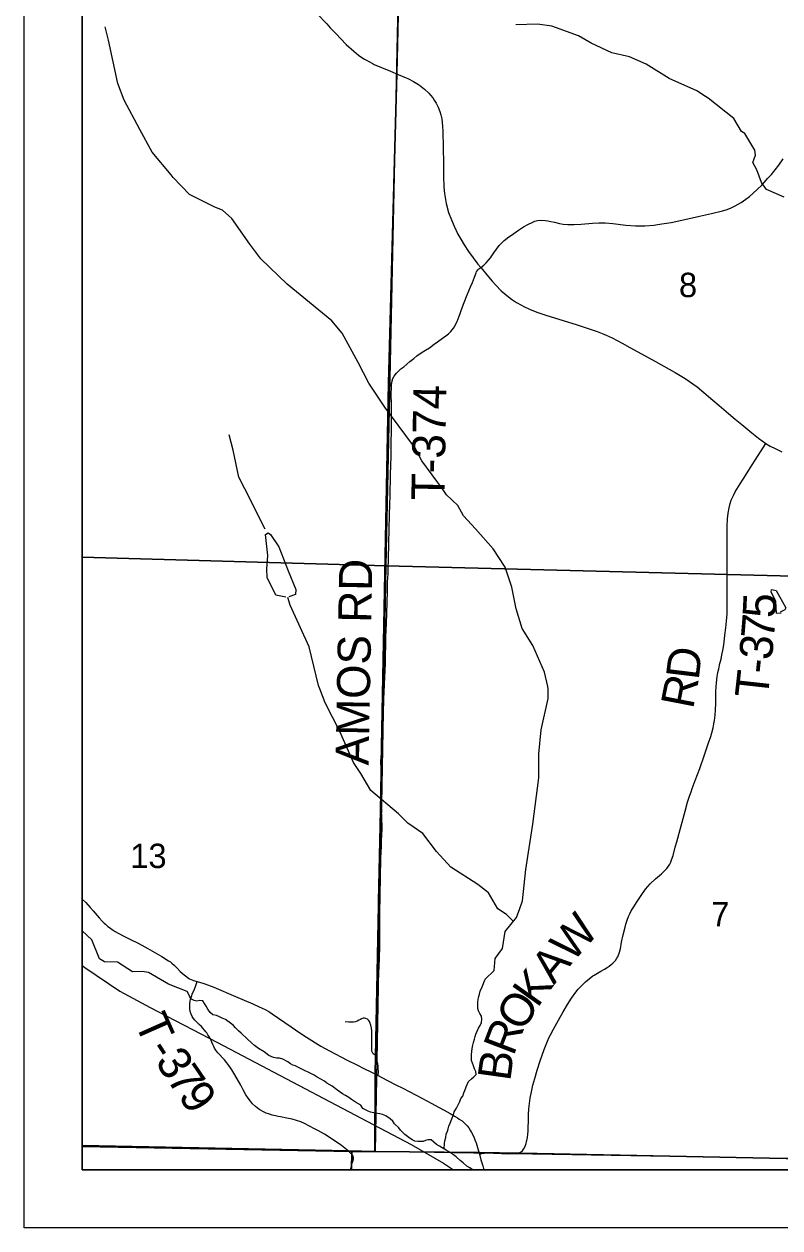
# Model space of a CAD drawing. Extents: x 0 to 34, y 0 to 22.
# Drawn here: x 2.5 to 3.798, y 13.5 to 15.568 of the extents above; entities that cross this region are included whole.
import ezdxf

# ---------------------------------------------------------------- set-up
doc = ezdxf.new("R2010")
doc.units = 0
for name, color, linetype in [('GM_X_Corporation', 7, 'Continuous'), ('GM_X_County_Road', 7, 'Continuous'), ('GM_X_Minor_River', 7, 'Continuous'), ('GM_X_Rail_Line', 7, 'Continuous'), ('GM_X_Section_Text', 7, 'Continuous'), ('GM_X_State_Route', 7, 'Continuous'), ('GM_X_Township_Road', 7, 'Continuous'), ('GM_X_Township_Road_Text', 7, 'Continuous'), ('SH_Data', 7, 'Continuous')]:
    doc.layers.add(name, color=color, linetype=linetype)

msp = doc.modelspace()

# ---------------------------------------------------------------- linework, layer by layer
at = {"layer": 'GM_X_Corporation'}
for points in [[(2.6, 16.6918), (2.6, 13.6), (9.4, 13.6), (9.4, 16.4853), (9.09, 16.4927), (8.0963, 16.5226), (6.2194, 16.578), (6.0834, 16.5816), (5.4202, 16.5982), (4.6351, 16.6229), (4.5473, 16.6256), (4.1867, 16.6352), (4.1011, 16.6362), (4.0515, 16.6368), (3.1684, 16.6682), (3.1555, 16.6686)], [(2.6, 16.6918), (2.6, 13.6417), (3.0575, 13.6324), (3.1025, 13.6315), (3.1033, 13.7653), (3.1089, 14.0542), (3.109, 14.0614), (3.1121, 14.2169), (3.1127, 14.2486), (3.1134, 14.2853), (3.1142, 14.3277), (3.1263, 14.9513), (3.1401, 15.483), (3.148, 15.8071), (3.1555, 16.6686)], [(2.6, 15.673), (2.6, 14.6526), (3.1218, 14.6372), (3.1435, 15.6571)], [(4.1616, 15.6255), (4.1372, 14.6117), (3.1218, 14.6372), (3.1435, 15.6571)], [(2.6, 14.6526), (2.6, 13.6399), (3.0633, 13.6314), (3.1037, 13.6311), (3.1218, 14.6372)], [(3.1218, 14.6372), (4.1372, 14.6117), (4.1159, 13.6143), (3.1037, 13.6311)], [(2.6, 13.6417), (2.6, 13.6), (4.5781, 13.6), (4.3222, 13.6092), (3.3525, 13.6282), (3.2812, 13.6297), (3.1025, 13.6315), (3.0575, 13.6324)], [(2.6, 13.6399), (2.6, 13.6), (3.0626, 13.6), (3.0633, 13.6314)], [(3.0626, 13.6), (4.1154, 13.6), (4.1159, 13.6143), (3.1037, 13.6311), (3.0633, 13.6314)]]:
    msp.add_lwpolyline(points, close=True, dxfattribs=at)
msp.add_lwpolyline([(3.1555, 16.6686), (3.148, 15.8071), (3.1401, 15.483), (3.1263, 14.9513), (3.1142, 14.3277), (3.1134, 14.2853), (3.1127, 14.2486), (3.1121, 14.2169), (3.109, 14.0614), (3.1089, 14.0542), (3.1033, 13.7653), (3.1025, 13.6315), (3.2812, 13.6297), (3.3525, 13.6282), (4.3222, 13.6092), (4.5781, 13.6), (9.4, 13.6)], dxfattribs=at)
at = {"layer": 'GM_X_County_Road'}
for points in [[(2.6, 14.065), (2.606, 14.0588), (2.6135, 14.0506), (2.6189, 14.0445), (2.6289, 14.0329), (2.6344, 14.0269), (2.6371, 14.0243), (2.6377, 14.0237), (2.6396, 14.0219), (2.6441, 14.0181), (2.6465, 14.0163), (2.6515, 14.0126), (2.6566, 14.0093), (2.6619, 14.0062), (2.6711, 14.0012), (2.6842, 13.9947), (2.6949, 13.9896), (2.7022, 13.986), (2.7128, 13.9803), (2.7208, 13.9756), (2.7365, 13.9665), (2.7483, 13.9591), (2.7515, 13.9569), (2.7538, 13.9551), (2.758, 13.9513), (2.7629, 13.9461), (2.7684, 13.9405), (2.7748, 13.9346), (2.7771, 13.9328), (2.7825, 13.9292), (2.7843, 13.9282), (2.7899, 13.9258), (2.7912, 13.9253), (2.7974, 13.9233), (2.7993, 13.9228), (2.8054, 13.9211), (2.8107, 13.9194), (2.8261, 13.9134), (2.8634, 13.8977), (2.8779, 13.8913), (2.8927, 13.885), (2.9038, 13.8801), (2.9142, 13.875), (2.9204, 13.8716), (2.9223, 13.8704), (2.9263, 13.8678), (2.9372, 13.8604), (2.9587, 13.8454), (2.9736, 13.8354), (2.9851, 13.8279), (3.01, 13.8124), (3.0245, 13.8041), (3.0548, 13.7884), (3.0715, 13.7799), (3.0847, 13.7735), (3.0956, 13.768), (3.1023, 13.7646)], [(3.1023, 13.7646), (3.1081, 13.7618), (3.1133, 13.7592), (3.1374, 13.7466), (3.1519, 13.7393), (3.1605, 13.7347), (3.1747, 13.7273), (3.2007, 13.7136), (3.2121, 13.7077), (3.2215, 13.7025), (3.232, 13.6965), (3.2403, 13.6915), (3.2444, 13.6889), (3.2474, 13.687), (3.2513, 13.6844), (3.2524, 13.6837), (3.2566, 13.6802), (3.2611, 13.6755), (3.264, 13.6717), (3.2669, 13.667), (3.2685, 13.6642), (3.2718, 13.6578), (3.2731, 13.6549), (3.2744, 13.6515), (3.2761, 13.6475), (3.2766, 13.6462), (3.28, 13.634), (3.2822, 13.6266)], [(3.2822, 13.6266), (3.2835, 13.6217), (3.2839, 13.6201), (3.2848, 13.6172)], [(3.2848, 13.6172), (3.2878, 13.6065), (3.2899, 13.6)]]:
    msp.add_lwpolyline(points, dxfattribs=at)
at = {"layer": 'GM_X_Minor_River'}
for points in [[(3.2868, 13.9142), (3.2923, 13.9274), (3.3076, 13.9424), (3.3092, 13.9629), (3.3218, 13.9802), (3.3263, 14.0094), (3.3461, 14.0332), (3.3516, 14.0488), (3.3563, 14.0622), (3.362, 14.1157), (3.3737, 14.1936), (3.3843, 14.273), (3.3841, 14.3143), (3.3884, 14.3557), (3.4001, 14.4097), (3.4003, 14.426), (3.3995, 14.4302), (3.3938, 14.4547), (3.3737, 14.5007), (3.3555, 14.5296), (3.3455, 14.5636), (3.3377, 14.601), (3.3266, 14.635), (3.306, 14.6665), (3.2752, 14.701), (3.2551, 14.7234), (3.245, 14.7411), (3.2254, 14.7594), (3.2188, 14.7695), (3.1835, 14.8179), (3.1714, 14.8408), (3.1675, 14.8461), (3.1199, 14.9102), (3.0924, 14.9515), (3.074, 14.9869), (3.0467, 15.0369), (3.0286, 15.0586), (2.9521, 15.1215), (2.9067, 15.1648), (2.8877, 15.1899), (2.8567, 15.2342), (2.8406, 15.2487), (2.8276, 15.2538), (2.784, 15.2752), (2.7563, 15.3043), (2.7528, 15.3092), (2.72, 15.3481), (2.6989, 15.3868), (2.672, 15.4376), (2.6609, 15.4662), (2.645, 15.5406), (2.6394, 15.5633)], [(3.8056, 15.2709), (3.7751, 15.2838), (3.7665, 15.2958), (3.7586, 15.318), (3.7516, 15.3304), (3.7567, 15.343), (3.7555, 15.3513), (3.7384, 15.3803), (3.7326, 15.3836), (3.719, 15.4058), (3.6749, 15.4411), (3.6706, 15.4437), (3.6557, 15.4537), (3.608, 15.4746), (3.5689, 15.4995), (3.5402, 15.5119), (3.5094, 15.5187), (3.4742, 15.5356), (3.4524, 15.5478), (3.4066, 15.5645), (3.3819, 15.568), (3.3448, 15.567)], [(2.9139, 14.7002), (2.8795, 14.7698), (2.869, 14.7897), (2.8592, 14.8362), (2.8523, 14.8626)], [(2.9498, 14.5836), (2.9323, 14.5871), (2.9174, 14.6172), (2.9172, 14.6324), (2.9188, 14.6551), (2.9148, 14.6915), (2.9193, 14.6942), (2.9235, 14.6912), (2.9379, 14.6702), (2.9537, 14.6291), (2.9667, 14.5967), (2.9664, 14.5884), (2.9547, 14.584)], [(3.3406, 14.0266), (3.329, 14.0386), (3.3136, 14.0483), (3.298, 14.0757), (3.2792, 14.0899), (3.2329, 14.1199), (3.2082, 14.1465), (3.185, 14.1776), (3.1593, 14.1954), (3.1431, 14.2111), (3.0955, 14.2517), (3.0787, 14.2807), (3.0659, 14.2994), (3.0424, 14.3529), (3.017, 14.4018), (3.0079, 14.4263), (3.0055, 14.432), (2.9898, 14.4985), (2.9572, 14.57), (2.9528, 14.5832)], [(3.8006, 14.5562), (3.7923, 14.5553), (3.7912, 14.5766), (3.7834, 14.5924), (3.7837, 14.5965), (3.7917, 14.5948), (3.8088, 14.5654), (3.807, 14.5616), (3.799, 14.5581)], [(2.7799, 13.9062), (2.7479, 13.9186), (2.7138, 13.9386), (2.7031, 13.9403), (2.6861, 13.9397), (2.6604, 13.9564), (2.6384, 13.9572), (2.6296, 13.9623), (2.6162, 13.9947), (2.6, 14.0101)], [(2.8838, 13.8242), (2.8731, 13.8348), (2.8685, 13.8385), (2.8631, 13.8438), (2.86, 13.8479), (2.8546, 13.8517), (2.8458, 13.8581), (2.8404, 13.8603), (2.8347, 13.8633), (2.8305, 13.8647), (2.824, 13.8658), (2.8194, 13.8703), (2.8159, 13.8756), (2.8128, 13.8809), (2.8097, 13.8854), (2.807, 13.89), (2.8021, 13.8907), (2.7968, 13.8898), (2.7922, 13.8906), (2.7876, 13.8928), (2.7845, 13.8972), (2.7822, 13.9021), (2.7799, 13.9062)], [(3.2216, 13.6357), (3.2224, 13.6449), (3.2228, 13.6498), (3.2246, 13.6556), (3.2253, 13.6609), (3.2272, 13.6662), (3.2283, 13.6704), (3.2297, 13.6746), (3.232, 13.68), (3.2349, 13.6876), (3.2379, 13.6941), (3.239, 13.6994), (3.2427, 13.7059), (3.245, 13.7101), (3.2487, 13.7174), (3.2505, 13.7223), (3.2539, 13.7265), (3.2554, 13.7319), (3.2569, 13.7361), (3.2595, 13.7422), (3.2609, 13.7464), (3.2632, 13.7517), (3.2685, 13.7563), (3.2726, 13.7594), (3.2767, 13.7636), (3.2759, 13.7689), (3.2736, 13.7735), (3.272, 13.7784), (3.2701, 13.7829), (3.2685, 13.7875), (3.2685, 13.7928), (3.2688, 13.7973), (3.2691, 13.8038), (3.2705, 13.8114), (3.272, 13.8186), (3.2735, 13.8244), (3.2749, 13.8289), (3.276, 13.8331), (3.2786, 13.8381), (3.2809, 13.843), (3.2835, 13.848), (3.2857, 13.853), (3.2864, 13.8587), (3.2856, 13.864), (3.2829, 13.8681), (3.2806, 13.8731), (3.2797, 13.8772), (3.2793, 13.8822), (3.2796, 13.8875), (3.2803, 13.8928), (3.2814, 13.8974), (3.2825, 13.9016), (3.2832, 13.9065), (3.2868, 13.9142)], [(3.2705, 13.6), (3.2697, 13.6005), (3.2655, 13.6032), (3.2605, 13.6061), (3.2544, 13.6118), (3.249, 13.6159), (3.2421, 13.6219), (3.2332, 13.6291), (3.2252, 13.6335), (3.2183, 13.6376), (3.2137, 13.6403), (3.2084, 13.6432), (3.2038, 13.6474), (3.1992, 13.6511), (3.1938, 13.6511), (3.1896, 13.6503), (3.1855, 13.6483), (3.1764, 13.6482), (3.1714, 13.649), (3.1668, 13.6516), (3.1607, 13.6553), (3.1538, 13.6606), (3.1469, 13.6677), (3.1438, 13.6722), (3.1365, 13.679), (3.1334, 13.6835), (3.1288, 13.6873), (3.1215, 13.6925), (3.1158, 13.6947), (3.1112, 13.6958), (3.1035, 13.6973), (3.0952, 13.6991), (3.0902, 13.701), (3.0818, 13.7054), (3.0783, 13.7111), (3.0691, 13.7159), (3.0622, 13.7204), (3.058, 13.7242), (3.0522, 13.7275), (3.0469, 13.7305), (3.0369, 13.7376), (3.0293, 13.7433), (3.0201, 13.7489), (3.0158, 13.7523), (3.0032, 13.759), (2.9986, 13.7627), (2.9902, 13.7664), (2.9806, 13.7709), (2.9703, 13.7761), (2.9661, 13.7787), (2.9619, 13.7798), (2.9577, 13.7817), (2.9531, 13.7851), (2.9447, 13.7899), (2.939, 13.7914), (2.934, 13.7917), (2.9287, 13.7928), (2.9206, 13.7961), (2.9122, 13.8025), (2.9026, 13.8081), (2.8961, 13.8134), (2.8907, 13.8179), (2.8838, 13.8242)]]:
    msp.add_lwpolyline(points, dxfattribs=at)
at = {"layer": 'GM_X_Rail_Line'}
msp.add_lwpolyline([(2.6, 13.9509), (2.6043, 13.9472), (2.6645, 13.9065), (2.7166, 13.8785), (2.8323, 13.8188), (3.1651, 13.6431), (3.2204, 13.6113), (3.2374, 13.6)], dxfattribs=at)
at = {"layer": 'GM_X_State_Route'}
for points in [[(3.0036, 15.5859), (3.0198, 15.5683), (3.026, 15.5619), (3.0353, 15.5522), (3.0534, 15.5332), (3.0666, 15.5215), (3.0745, 15.5149), (3.0767, 15.5133), (3.085, 15.508), (3.0869, 15.5068), (3.0996, 15.4998), (3.1012, 15.4989), (3.114, 15.4933), (3.1293, 15.487), (3.1425, 15.4814)], [(3.1425, 15.4814), (3.1533, 15.4772), (3.1553, 15.4763), (3.1604, 15.4739), (3.1687, 15.4697), (3.1774, 15.4646), (3.1794, 15.4632), (3.1881, 15.4566), (3.1954, 15.4494), (3.1983, 15.4461), (3.2022, 15.4412), (3.2044, 15.4377), (3.2077, 15.4325), (3.2111, 15.4255), (3.214, 15.418), (3.2158, 15.4123), (3.2174, 15.4051), (3.2183, 15.3988), (3.2188, 15.3928), (3.2193, 15.3836), (3.2196, 15.3722), (3.2197, 15.3677), (3.2198, 15.3587), (3.2203, 15.3259), (3.2207, 15.2998), (3.2208, 15.2952), (3.2212, 15.2879), (3.2221, 15.277), (3.2231, 15.27), (3.2249, 15.2598), (3.2293, 15.2443), (3.234, 15.2319), (3.2389, 15.2208), (3.245, 15.2075), (3.2501, 15.1984), (3.2561, 15.1887), (3.2637, 15.1776), (3.2713, 15.1667), (3.2777, 15.158), (3.2795, 15.1557), (3.2846, 15.1499), (3.2873, 15.1465), (3.2949, 15.1371), (3.3042, 15.1264), (3.3106, 15.1194), (3.3197, 15.11), (3.3257, 15.1047), (3.332, 15.0997), (3.3372, 15.0958), (3.3393, 15.0943), (3.3444, 15.091), (3.3461, 15.0898), (3.3544, 15.085), (3.3586, 15.0828), (3.3683, 15.0783), (3.381, 15.0734), (3.3965, 15.0681), (3.4129, 15.0628), (3.4483, 15.0518), (3.4671, 15.0457), (3.4847, 15.0398), (3.4961, 15.0354), (3.5002, 15.0336), (3.5101, 15.029), (3.5277, 15.0198), (3.5408, 15.0127), (3.5732, 14.9947), (3.5847, 14.9883), (3.6083, 14.9752), (3.6182, 14.9695), (3.6273, 14.9642), (3.6356, 14.959), (3.643, 14.9542), (3.6488, 14.9502), (3.656, 14.9448), (3.6678, 14.9352), (3.6757, 14.9284), (3.6833, 14.9218), (3.6939, 14.913), (3.71, 14.8993), (3.7218, 14.8894), (3.7329, 14.8804), (3.75, 14.8661), (3.7618, 14.8569), (3.7677, 14.8522), (3.7742, 14.8478), (3.7816, 14.8433), (3.7903, 14.8388), (3.8019, 14.8332)]]:
    msp.add_lwpolyline(points, dxfattribs=at)
at = {"layer": 'GM_X_Township_Road'}
for points in [[(3.2846, 15.1499), (3.2897, 15.1541), (3.2938, 15.1579), (3.2976, 15.1624), (3.3011, 15.1668), (3.307, 15.1751), (3.3164, 15.1878), (3.3205, 15.1922), (3.3248, 15.1963), (3.3328, 15.2025), (3.3371, 15.2057), (3.3493, 15.2141), (3.3582, 15.2199), (3.3665, 15.2246), (3.3726, 15.2274), (3.3775, 15.2293), (3.3818, 15.2305), (3.3865, 15.2311), (3.3954, 15.2308), (3.3995, 15.2302), (3.4049, 15.2292), (3.4114, 15.2278), (3.4197, 15.2257), (3.4263, 15.2246), (3.434, 15.2238), (3.445, 15.2236), (3.4571, 15.2243), (3.4764, 15.2261), (3.4874, 15.2268), (3.4982, 15.2266), (3.5112, 15.2256), (3.5339, 15.2229), (3.5506, 15.2216), (3.5664, 15.2218), (3.5818, 15.2228), (3.5955, 15.2247), (3.6116, 15.2275), (3.6348, 15.2323), (3.66, 15.238), (3.681, 15.2428), (3.6999, 15.2472), (3.7062, 15.249), (3.7134, 15.252), (3.7217, 15.2561), (3.7318, 15.2619), (3.74, 15.2676), (3.7459, 15.272), (3.7521, 15.2773), (3.7673, 15.2915), (3.7747, 15.3), (3.7771, 15.3027), (3.7815, 15.3073), (3.7837, 15.3098), (3.7963, 15.3258), (3.8041, 15.3364)], [(3.1316, 14.9514), (3.1323, 14.9552), (3.1337, 14.959), (3.1358, 14.9635), (3.1398, 14.9687), (3.1473, 14.9756), (3.1522, 14.9795), (3.1575, 14.9841), (3.1629, 14.9885), (3.1693, 14.9939), (3.1748, 14.9981), (3.1824, 15.0032), (3.1897, 15.0077), (3.1964, 15.0122), (3.2047, 15.0181), (3.2103, 15.0221), (3.219, 15.0283), (3.2244, 15.0324), (3.2289, 15.0362), (3.2329, 15.0402), (3.2374, 15.0455), (3.2392, 15.048), (3.2418, 15.0529), (3.2437, 15.0572), (3.2491, 15.0707), (3.2511, 15.0763), (3.2534, 15.0826), (3.2561, 15.0896), (3.2612, 15.1028), (3.267, 15.1167), (3.2701, 15.124), (3.2736, 15.1336), (3.2764, 15.141), (3.2772, 15.1428), (3.2781, 15.1442), (3.2795, 15.1459), (3.2813, 15.1475), (3.2846, 15.1499)], [(3.1053, 13.7957), (3.1052, 13.799), (3.1065, 13.8326), (3.1071, 13.8478), (3.1077, 13.8747), (3.1081, 13.9189), (3.1087, 13.9275), (3.11, 13.9492), (3.1105, 13.9633), (3.1112, 13.9834), (3.1111, 14.0021), (3.1109, 14.0178), (3.1111, 14.0392), (3.1104, 14.0616), (3.1099, 14.0772), (3.1104, 14.0983), (3.1113, 14.1089), (3.1123, 14.1207), (3.1128, 14.1269), (3.1131, 14.1362), (3.1136, 14.1446), (3.1141, 14.156), (3.1142, 14.1654), (3.1147, 14.1747), (3.1151, 14.1868), (3.1143, 14.2058), (3.1141, 14.2167), (3.1135, 14.2348), (3.1133, 14.2572), (3.1138, 14.2743), (3.1127, 14.3019), (3.1139, 14.3158), (3.1151, 14.3342), (3.1158, 14.3499), (3.1172, 14.3836), (3.1176, 14.3924), (3.1178, 14.4009), (3.118, 14.4102), (3.1185, 14.4198), (3.1191, 14.4333), (3.1199, 14.4463), (3.1206, 14.4693), (3.1208, 14.4809), (3.1213, 14.5026), (3.1217, 14.5161), (3.1226, 14.5381), (3.124, 14.5747), (3.1242, 14.5945), (3.1245, 14.6098), (3.1253, 14.6239), (3.1256, 14.635), (3.1259, 14.6462), (3.1262, 14.6573), (3.1265, 14.6673), (3.1266, 14.6843), (3.1269, 14.6922), (3.1272, 14.699), (3.1276, 14.7254), (3.1283, 14.742), (3.1286, 14.7585), (3.129, 14.7649), (3.1293, 14.7871), (3.1297, 14.7976), (3.1299, 14.8062), (3.1306, 14.8297), (3.1307, 14.8479), (3.1311, 14.8707), (3.1313, 14.8796), (3.1311, 14.8943), (3.1314, 14.91), (3.1311, 14.9159), (3.1307, 14.931), (3.131, 14.945), (3.1314, 14.9504), (3.1316, 14.9514)], [(3.3631, 13.6483), (3.3636, 13.6504), (3.3646, 13.6554), (3.3655, 13.6608), (3.366, 13.6665), (3.3661, 13.6704), (3.3663, 13.6855), (3.3666, 13.695), (3.3672, 13.7045), (3.3682, 13.7139), (3.3694, 13.7228), (3.3714, 13.7336), (3.3742, 13.7455), (3.3774, 13.7568), (3.3815, 13.7713), (3.3868, 13.7869), (3.3935, 13.8067), (3.3992, 13.821), (3.4021, 13.8275), (3.4041, 13.8316), (3.4094, 13.8415), (3.4178, 13.857), (3.4259, 13.8711), (3.4335, 13.8837), (3.4406, 13.8947), (3.4479, 13.9052), (3.4518, 13.9099), (3.4556, 13.914), (3.4602, 13.9188), (3.4643, 13.9227), (3.471, 13.9282), (3.4773, 13.9328), (3.4791, 13.934), (3.4905, 13.9409), (3.4972, 13.9448), (3.5015, 13.9475), (3.5052, 13.9498), (3.5087, 13.9524), (3.5114, 13.9546), (3.5138, 13.9569), (3.516, 13.9596), (3.5185, 13.9632), (3.5199, 13.9659), (3.5224, 13.9721), (3.5244, 13.9793), (3.5265, 13.9907), (3.5294, 14.0036), (3.5324, 14.0167), (3.5339, 14.0219), (3.5361, 14.0285), (3.5385, 14.0349), (3.5404, 14.0398), (3.5429, 14.0447), (3.5472, 14.0518), (3.5523, 14.0591), (3.56, 14.0712), (3.5675, 14.0818), (3.5715, 14.0866), (3.5756, 14.0909), (3.5849, 14.0997), (3.5947, 14.1085), (3.5992, 14.1125), (3.6039, 14.1176), (3.6069, 14.1212), (3.6093, 14.1251), (3.6108, 14.1286), (3.6124, 14.1325), (3.6148, 14.1398), (3.6186, 14.1541), (3.6211, 14.1633), (3.6287, 14.1905), (3.6356, 14.2161), (3.6399, 14.2312), (3.6433, 14.242), (3.6458, 14.2493), (3.6478, 14.2549), (3.6531, 14.2688), (3.6606, 14.2893), (3.6681, 14.3112), (3.672, 14.3228), (3.6759, 14.3335), (3.6796, 14.3441), (3.6815, 14.3503), (3.6838, 14.3594), (3.6851, 14.366), (3.6861, 14.3719), (3.6871, 14.3807), (3.6878, 14.39), (3.6882, 14.4009), (3.6885, 14.4208), (3.6889, 14.4301), (3.6893, 14.436), (3.6899, 14.4423), (3.6906, 14.4473), (3.6918, 14.4543), (3.6932, 14.4607), (3.6953, 14.4699), (3.6972, 14.477), (3.6989, 14.4847), (3.7003, 14.4918), (3.7013, 14.4983), (3.7024, 14.5065), (3.704, 14.5186), (3.7054, 14.5309), (3.7066, 14.5421), (3.7076, 14.5547), (3.7079, 14.5687), (3.708, 14.5938), (3.7078, 14.6207), (3.7079, 14.6695), (3.708, 14.7055), (3.7086, 14.718), (3.7095, 14.7279), (3.711, 14.7371), (3.7128, 14.7447), (3.7148, 14.7505), (3.7167, 14.755), (3.7185, 14.7585), (3.7218, 14.7644), (3.7302, 14.7782), (3.7353, 14.7866), (3.7449, 14.8017), (3.7509, 14.8107), (3.7561, 14.8188), (3.7702, 14.8414), (3.7742, 14.8478)], [(3.0568, 13.6325), (3.0454, 13.6416), (3.0292, 13.6526), (3.0159, 13.661), (3.0112, 13.6638), (3.0057, 13.6667), (2.9991, 13.6703), (2.982, 13.6792), (2.9753, 13.682), (2.9681, 13.6845), (2.9605, 13.6866), (2.9515, 13.6887), (2.9406, 13.6906), (2.9365, 13.6914), (2.9321, 13.6923), (2.9262, 13.6938), (2.9214, 13.6952), (2.9159, 13.6973), (2.9112, 13.6993), (2.9048, 13.7028), (2.903, 13.7041), (2.8976, 13.7086), (2.8924, 13.7134), (2.8889, 13.7176), (2.8865, 13.7205), (2.8838, 13.7244), (2.881, 13.7288), (2.8763, 13.7371), (2.8721, 13.7451), (2.862, 13.7628), (2.8571, 13.7714), (2.8547, 13.7751), (2.8517, 13.7793), (2.8484, 13.7835), (2.8441, 13.7885), (2.8328, 13.8008), (2.8292, 13.8051), (2.8271, 13.8087), (2.8257, 13.8116), (2.8242, 13.8153), (2.8225, 13.8192), (2.8201, 13.8246), (2.8173, 13.8295), (2.8159, 13.832), (2.8137, 13.8352), (2.8124, 13.8369), (2.8048, 13.8458), (2.8008, 13.8497), (2.7936, 13.857), (2.7909, 13.8599), (2.7888, 13.8633), (2.7868, 13.8673), (2.7851, 13.8717), (2.7845, 13.8768), (2.7846, 13.8813), (2.7849, 13.8857), (2.7852, 13.8894), (2.786, 13.8932), (2.7876, 13.8976), (2.7896, 13.9033), (2.7919, 13.9087), (2.7948, 13.9163), (2.7974, 13.9233)], [(3.1053, 13.7957), (3.1034, 13.7966), (3.1013, 13.7977), (3.0998, 13.7991), (3.0984, 13.8014), (3.0976, 13.8038), (3.0975, 13.8082), (3.0976, 13.8176), (3.0975, 13.8241), (3.0974, 13.8379), (3.0967, 13.8432), (3.0957, 13.8482), (3.0942, 13.8527), (3.0932, 13.8548), (3.0914, 13.8571), (3.0899, 13.8586), (3.0872, 13.8599), (3.0848, 13.8603), (3.0823, 13.8601), (3.0798, 13.8594), (3.0778, 13.8583), (3.0752, 13.8568), (3.0721, 13.8552), (3.0695, 13.8541), (3.0659, 13.8535), (3.0622, 13.8534), (3.0577, 13.8536), (3.0513, 13.8541)], [(3.1081, 13.7618), (3.1089, 13.7675), (3.1085, 13.7753), (3.1081, 13.7787), (3.1075, 13.7819), (3.106, 13.7898), (3.1055, 13.7928), (3.1053, 13.7957)], [(3.0609, 13.6), (3.062, 13.6046), (3.0637, 13.6111), (3.0653, 13.6161), (3.0657, 13.6181), (3.0659, 13.6197), (3.0657, 13.6212), (3.0651, 13.6232), (3.0645, 13.6245), (3.0628, 13.6269), (3.061, 13.6287), (3.0568, 13.6325)], [(3.2822, 13.6266), (3.2887, 13.6283), (3.2908, 13.6287), (3.2933, 13.6289), (3.2959, 13.629), (3.3321, 13.6275), (3.3443, 13.6276), (3.3476, 13.6281), (3.3501, 13.6288), (3.353, 13.6303), (3.3561, 13.6327), (3.3582, 13.6353), (3.3597, 13.6377), (3.3609, 13.6404), (3.3624, 13.645), (3.3631, 13.6483)]]:
    msp.add_lwpolyline(points, dxfattribs=at)
at = {"layer": 'SH_Data'}
for points in [[(2.5, 20.5), (9.5, 20.5), (9.5, 13.5), (2.5, 13.5)], [(2.6, 20.4), (9.4, 20.4), (9.4, 13.6), (2.6, 13.6)]]:
    msp.add_lwpolyline(points, close=True, dxfattribs=at)

# ---------------------------------------------------------------- texts
at = {"layer": 'GM_X_Section_Text'}
for s, height, p in [('8', 0.0419, (3.625, 15.099)), ('13', 0.04186, (2.6825, 14.1182)), ('7', 0.0419, (3.6804, 14.0179))]:
    msp.add_text(s, height=height, rotation=0, dxfattribs=at).set_placement(p)
at = {"layer": 'GM_X_Township_Road_Text'}
for s, height, rotation, p in [('T-374', 0.05682, 88.8762, (3.2219, 14.7495)), ('AMOS RD', 0.05682, 88.9363, (3.0918, 14.2944)), ('5', 0.0568, 87.1865, (3.7908, 14.547)), ('7', 0.0568, 85.439, (3.7879, 14.5102)), ('3', 0.0568, 84.4037, (3.7844, 14.4743)), ('D', 0.0568, 83.048, (3.6587, 14.4402)), ('T', 0.0568, 83.6787, (3.7772, 14.4081)), ('-', 0.0568, 83.8459, (3.7819, 14.4505)), ('R', 0.0568, 79.0161, (3.6491, 14.3901)), ('W', 0.0568, 48.7157, (3.4419, 13.9545)), ('A', 0.0568, 50.1095, (3.4101, 13.9165)), ('K', 0.0568, 54.6093, (3.3818, 13.8766)), ('O', 0.0568, 58.2684, (3.356, 13.8349)), ('T', 0.0568, 293.9442, (2.689, 13.8532)), ('R', 0.0568, 69.0241, (3.3406, 13.7939)), ('-', 0.0568, 302.9726, (2.7109, 13.8058)), ('3', 0.0568, 303.6007, (2.7239, 13.7857)), ('B', 0.0568, 82.0951, (3.335, 13.7509)), ('7', 0.0568, 304.1812, (2.7437, 13.756)), ('9', 0.0568, 304.3455, (2.7634, 13.7269))]:
    msp.add_text(s, height=height, rotation=rotation, dxfattribs=at).set_placement(p)

doc.saveas('drawing.dxf')
